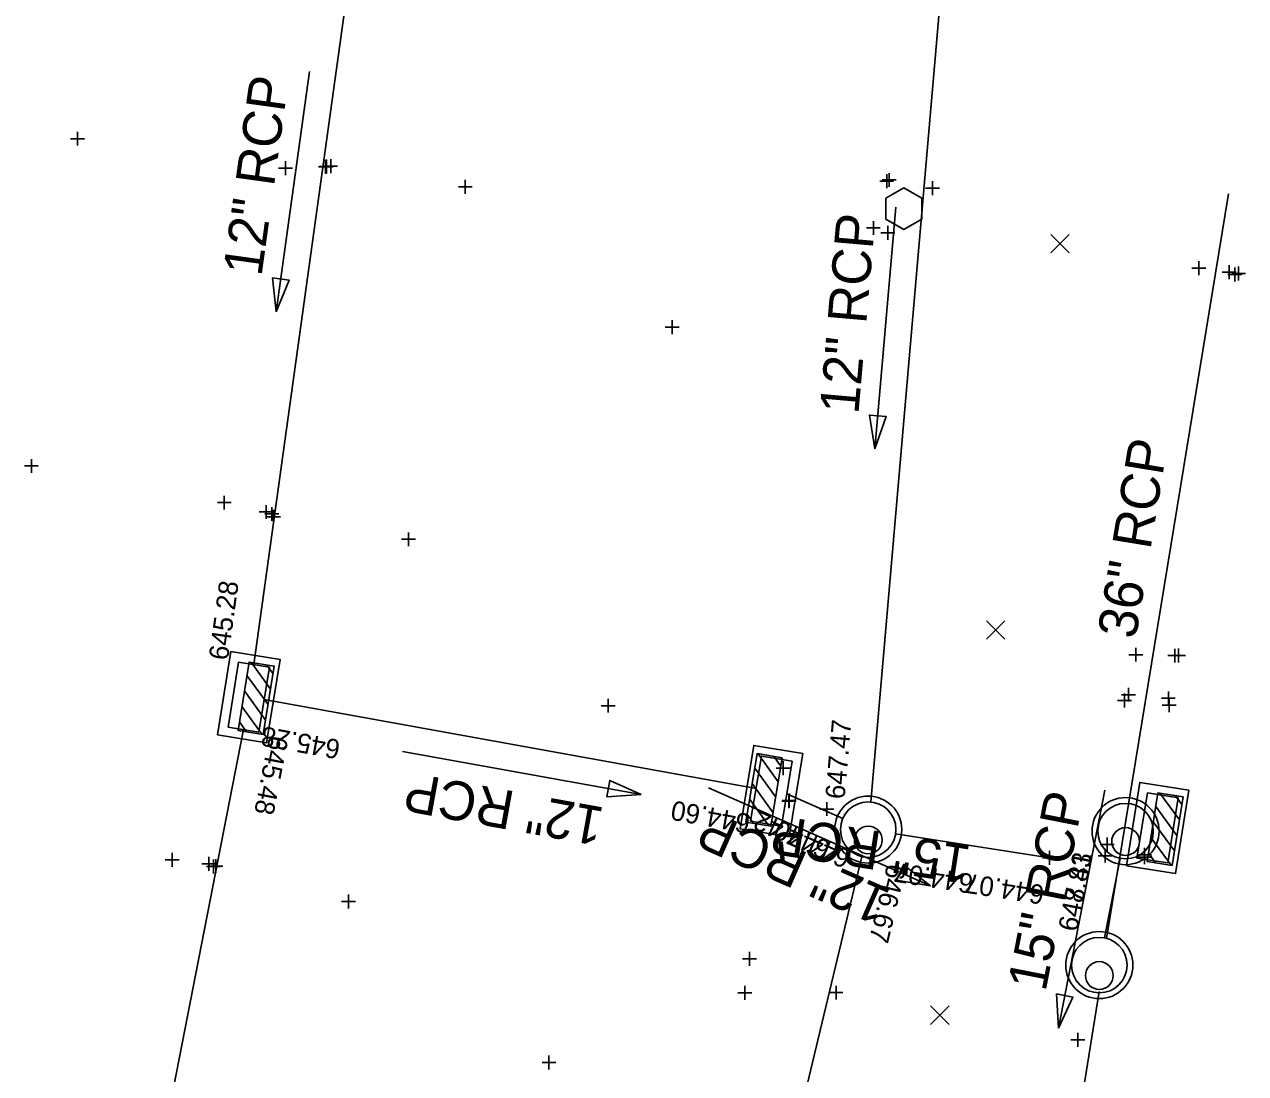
# Model space of a CAD drawing. Extents: x 2188719 to 2189819, y 654569 to 659504.
# Drawn here: x 2189545.4 to 2189633.4, y 656329.9 to 656405.5 of the extents above; entities that cross this region are included whole.
import ezdxf

# ---------------------------------------------------------------- set-up
doc = ezdxf.new("R2010")
doc.units = 0
for name, color, linetype in [('DR_X_Cells', 7, 'Continuous'), ('DR_X_Elev_Flow', 7, 'Continuous'), ('DR_X_Storm_Sewer', 7, 'Continuous'), ('DR_X_Text', 7, 'Continuous'), ('GK_Drainage_Nodes', 7, 'Continuous'), ('RD_X_Cells', 7, 'Continuous'), ('SC_Scratch1', 7, 'Continuous'), ('SV_X_Random_Point', 7, 'Continuous'), ('SV_X_Shot_Marker', 7, 'Continuous')]:
    doc.layers.add(name, color=color, linetype=linetype)

msp = doc.modelspace()

# ---------------------------------------------------------------- linework, layer by layer
at = {"layer": 'DR_X_Cells'}
for p, q in [((2189563.154, 656357.596), (2189561.755, 656359.529)), ((2189562.974, 656356.481), (2189561.456, 656358.578)), ((2189563.334, 656358.711), (2189562.874, 656359.348)), ((2189562.793, 656355.365), (2189561.275, 656357.463)), ((2189562.551, 656354.335), (2189561.095, 656356.348)), ((2189561.433, 656354.516), (2189560.914, 656355.232)), ((2189598.288, 656352.938), (2189599.736, 656350.92)), ((2189599.406, 656352.753), (2189599.921, 656352.035)), ((2189598.042, 656351.909), (2189599.551, 656349.805)), ((2189597.857, 656350.794), (2189599.366, 656348.691)), ((2189628.635, 656348.167), (2189627.233, 656350.098)), ((2189628.814, 656349.283), (2189628.352, 656349.919)), ((2189597.672, 656349.68), (2189599.063, 656347.741)), ((2189628.457, 656347.052), (2189626.935, 656349.147)), ((2189597.487, 656348.565), (2189597.945, 656347.927)), ((2189628.278, 656345.936), (2189626.757, 656348.031)), ((2189628.038, 656344.906), (2189626.578, 656346.915)), ((2189626.919, 656345.085), (2189626.4, 656345.8))]:
    msp.add_line(p, q, dxfattribs=at)
for points in [[(2189559.329, 656354.308), (2189560.301, 656360.313), (2189563.839, 656359.741), (2189562.867, 656353.735)], [(2189560.094, 656354.859), (2189560.853, 656359.548), (2189563.074, 656359.189), (2189562.315, 656354.5)], [(2189560.815, 656354.616), (2189561.613, 656359.552), (2189563.423, 656359.259), (2189562.624, 656354.323)], [(2189601.51, 656352.953), (2189600.515, 656346.951), (2189596.979, 656347.538), (2189597.974, 656353.539)], [(2189600.023, 656352.65), (2189599.205, 656347.718), (2189597.396, 656348.018), (2189598.215, 656352.95)], [(2189600.743, 656352.404), (2189599.965, 656347.718), (2189597.746, 656348.087), (2189598.523, 656352.772)], [(2189624.816, 656344.873), (2189625.777, 656350.879), (2189629.316, 656350.313), (2189628.355, 656344.306)], [(2189625.58, 656345.425), (2189626.331, 656350.116), (2189628.552, 656349.76), (2189627.802, 656345.07)], [(2189626.301, 656345.183), (2189627.091, 656350.121), (2189628.901, 656349.831), (2189628.111, 656344.894)]]:
    msp.add_lwpolyline(points, close=True, dxfattribs=at)
for centre, radius in [((2189606.217, 656347.475), 2.417), ((2189624.757, 656347.364), 2.417), ((2189606.217, 656347.475), 2), ((2189624.757, 656347.364), 2), ((2189606.217, 656346.725), 1), ((2189624.757, 656346.614), 1), ((2189622.866, 656337.708), 2.417), ((2189622.866, 656337.708), 2), ((2189622.866, 656336.958), 1)]:
    msp.add_circle(centre, radius, dxfattribs=at)
at = {"layer": 'DR_X_Elev_Flow'}
for p, q in [((2189618.782, 656345.442), (2189619.782, 656345.442)), ((2189619.282, 656345.942), (2189619.282, 656344.942)), ((2189619.282, 656345.442), (2189619.282, 656345.442)), ((2189603.396, 656335.723), (2189604.396, 656335.723)), ((2189603.896, 656336.223), (2189603.896, 656335.223)), ((2189603.896, 656335.723), (2189603.896, 656335.723))]:
    msp.add_line(p, q, dxfattribs=at)
at = {"layer": 'DR_X_Storm_Sewer'}
for p, q in [((2189571.657, 656429.364), (2189561.964, 656359.369)), ((2189612.494, 656419.834), (2189606.404, 656349.466)), ((2189623.386, 656339.617), (2189632.167, 656393.304)), ((2189562.695, 656356.844), (2189598.134, 656350.429)), ((2189547.183, 656282.894), (2189561.205, 656354.68)), ((2189600.354, 656350.061), (2189604.387, 656348.282)), ((2189608.193, 656347.168), (2189619.282, 656345.442)), ((2189589.745, 656278.758), (2189605.751, 656345.53)), ((2189624.373, 656345.401), (2189623.25, 656339.671)), ((2189622.866, 656335.815), (2189616.759, 656298.323))]:
    msp.add_line(p, q, dxfattribs=at)
at = {"layer": 'DR_X_Text'}
for p, q in [((2189565.963, 656402.099), (2189563.564, 656384.778)), ((2189608.207, 656392.329), (2189606.699, 656374.908)), ((2189572.654, 656353.111), (2189589.86, 656349.996)), ((2189594.702, 656350.478), (2189610.701, 656343.42)), ((2189623.274, 656350.328), (2189619.913, 656333.167))]:
    msp.add_line(p, q, dxfattribs=at)
for points in [[(2189563.564, 656384.778), (2189563.299, 656387.237), (2189564.488, 656387.073)], [(2189606.699, 656374.908), (2189606.308, 656377.351), (2189607.504, 656377.247)], [(2189589.86, 656349.996), (2189587.392, 656349.833), (2189587.605, 656351.014)], [(2189610.701, 656343.42), (2189608.263, 656343.84), (2189608.747, 656344.938)], [(2189619.913, 656333.167), (2189619.786, 656335.638), (2189620.963, 656335.407)]]:
    msp.add_lwpolyline(points, close=True, dxfattribs=at)
at = {"layer": 'GK_Drainage_Nodes'}
for p, q in [((2189561.964, 656359.369), (2189561.964, 656359.369)), ((2189559.816, 656357.31), (2189559.816, 656357.31)), ((2189560.474, 656357.204), (2189560.474, 656357.204)), ((2189561.214, 656357.084), (2189561.214, 656357.084)), ((2189561.214, 656357.084), (2189561.214, 656357.084)), ((2189561.584, 656357.024), (2189561.584, 656357.024)), ((2189562.695, 656356.844), (2189562.695, 656356.844)), ((2189563.353, 656356.738), (2189563.353, 656356.738)), ((2189561.205, 656354.68), (2189561.205, 656354.68)), ((2189599.633, 656352.588), (2189599.633, 656352.588)), ((2189597.477, 656350.539), (2189597.477, 656350.539)), ((2189598.134, 656350.429), (2189598.134, 656350.429)), ((2189599.244, 656350.245), (2189599.244, 656350.245)), ((2189599.614, 656350.184), (2189599.614, 656350.184)), ((2189599.614, 656350.184), (2189599.614, 656350.184)), ((2189600.354, 656350.061), (2189600.354, 656350.061)), ((2189601.012, 656349.952), (2189601.012, 656349.952)), ((2189627.442, 656349.938), (2189627.442, 656349.938)), ((2189606.217, 656349.475), (2189606.217, 656349.475)), ((2189624.757, 656349.364), (2189624.757, 656349.364)), ((2189598.855, 656347.902), (2189598.855, 656347.902)), ((2189606.217, 656347.475), (2189606.217, 656347.475)), ((2189606.217, 656347.475), (2189606.217, 656347.475)), ((2189624.757, 656347.364), (2189624.757, 656347.364)), ((2189624.757, 656347.364), (2189624.757, 656347.364)), ((2189625.297, 656347.876), (2189625.297, 656347.876)), ((2189625.955, 656347.771), (2189625.955, 656347.771)), ((2189626.696, 656347.652), (2189626.696, 656347.652)), ((2189626.696, 656347.652), (2189626.696, 656347.652)), ((2189627.066, 656347.593), (2189627.066, 656347.593)), ((2189628.177, 656347.415), (2189628.177, 656347.415)), ((2189628.835, 656347.31), (2189628.835, 656347.31)), ((2189606.217, 656346.725), (2189606.217, 656346.725)), ((2189624.757, 656346.614), (2189624.757, 656346.614)), ((2189606.217, 656345.475), (2189606.217, 656345.475)), ((2189624.757, 656345.364), (2189624.757, 656345.364)), ((2189626.691, 656345.248), (2189626.691, 656345.248)), ((2189622.866, 656339.708), (2189622.866, 656339.708)), ((2189622.866, 656337.708), (2189622.866, 656337.708)), ((2189622.866, 656337.708), (2189622.866, 656337.708)), ((2189622.866, 656336.958), (2189622.866, 656336.958)), ((2189622.866, 656335.708), (2189622.866, 656335.708))]:
    msp.add_line(p, q, dxfattribs=at)
for centre in [(2189606.217, 656347.475), (2189624.757, 656347.364), (2189622.866, 656337.708)]:
    msp.add_circle(centre, 2, dxfattribs=at)
at = {"layer": 'RD_X_Cells'}
msp.add_lwpolyline([(2189607.49, 656391.47), (2189608.788, 656390.72), (2189610.086, 656391.47), (2189610.086, 656392.97), (2189608.788, 656393.72), (2189607.49, 656392.97), (2189607.49, 656391.47)], dxfattribs=at)
at = {"layer": 'SV_X_Random_Point'}
for p, q in [((2189619.361, 656389.034), (2189620.695, 656390.368)), ((2189619.361, 656390.368), (2189620.695, 656389.034)), ((2189614.728, 656361.194), (2189616.062, 656362.529)), ((2189614.728, 656362.529), (2189616.062, 656361.194)), ((2189610.711, 656333.438), (2189612.045, 656334.772)), ((2189610.711, 656334.772), (2189612.045, 656333.438))]:
    msp.add_line(p, q, dxfattribs=at)
at = {"layer": 'SV_X_Shot_Marker'}
for p, q in [((2189548.743, 656397.266), (2189549.743, 656397.266)), ((2189549.243, 656397.766), (2189549.243, 656396.766)), ((2189549.243, 656397.266), (2189549.243, 656397.266)), ((2189564.23, 656395.64), (2189564.23, 656394.64)), ((2189567.117, 656395.739), (2189567.117, 656394.739)), ((2189567.18, 656395.761), (2189567.18, 656394.761)), ((2189567.488, 656395.781), (2189567.488, 656394.781)), ((2189563.73, 656395.14), (2189564.73, 656395.14)), ((2189564.23, 656395.14), (2189564.23, 656395.14)), ((2189566.617, 656395.239), (2189567.617, 656395.239)), ((2189566.68, 656395.261), (2189567.68, 656395.261)), ((2189566.988, 656395.281), (2189567.988, 656395.281)), ((2189567.117, 656395.239), (2189567.117, 656395.239)), ((2189567.18, 656395.261), (2189567.18, 656395.261)), ((2189567.488, 656395.281), (2189567.488, 656395.281)), ((2189607.548, 656394.709), (2189607.548, 656393.709)), ((2189607.721, 656394.79), (2189607.721, 656393.79)), ((2189576.687, 656393.8), (2189577.687, 656393.8)), ((2189577.187, 656394.3), (2189577.187, 656393.3)), ((2189577.187, 656393.8), (2189577.187, 656393.8)), ((2189607.048, 656394.209), (2189608.048, 656394.209)), ((2189607.221, 656394.29), (2189608.221, 656394.29)), ((2189607.548, 656394.209), (2189607.548, 656394.209)), ((2189607.721, 656394.29), (2189607.721, 656394.29)), ((2189610.849, 656394.198), (2189610.849, 656393.198)), ((2189610.349, 656393.698), (2189611.349, 656393.698)), ((2189610.849, 656393.698), (2189610.849, 656393.698)), ((2189606.585, 656391.334), (2189606.585, 656390.334)), ((2189606.085, 656390.834), (2189607.085, 656390.834)), ((2189606.585, 656390.834), (2189606.585, 656390.834)), ((2189607.127, 656390.474), (2189608.127, 656390.474)), ((2189607.627, 656390.974), (2189607.627, 656389.974)), ((2189607.627, 656390.474), (2189607.627, 656390.474)), ((2189629.54, 656387.942), (2189630.54, 656387.942)), ((2189630.04, 656388.442), (2189630.04, 656387.442)), ((2189630.04, 656387.942), (2189630.04, 656387.942)), ((2189631.714, 656387.649), (2189632.714, 656387.649)), ((2189632.214, 656388.149), (2189632.214, 656387.149)), ((2189632.214, 656387.649), (2189632.214, 656387.649)), ((2189632.636, 656387.983), (2189632.636, 656386.983)), ((2189632.903, 656388.045), (2189632.903, 656387.045)), ((2189632.136, 656387.483), (2189633.136, 656387.483)), ((2189632.403, 656387.545), (2189633.403, 656387.545)), ((2189632.636, 656387.483), (2189632.636, 656387.483)), ((2189632.903, 656387.545), (2189632.903, 656387.545)), ((2189592.086, 656384.182), (2189592.086, 656383.182)), ((2189591.586, 656383.682), (2189592.586, 656383.682)), ((2189592.086, 656383.682), (2189592.086, 656383.682)), ((2189545.424, 656373.679), (2189546.424, 656373.679)), ((2189545.924, 656374.179), (2189545.924, 656373.179)), ((2189545.924, 656373.679), (2189545.924, 656373.679)), ((2189559.325, 656371.037), (2189560.325, 656371.037)), ((2189559.825, 656371.537), (2189559.825, 656370.537)), ((2189559.825, 656371.037), (2189559.825, 656371.037)), ((2189562.84, 656370.864), (2189562.84, 656369.864)), ((2189562.34, 656370.364), (2189563.34, 656370.364)), ((2189562.743, 656370.223), (2189563.743, 656370.223)), ((2189562.84, 656370.364), (2189562.84, 656370.364)), ((2189562.872, 656370.011), (2189563.872, 656370.011)), ((2189563.243, 656370.723), (2189563.243, 656369.723)), ((2189563.243, 656370.223), (2189563.243, 656370.223)), ((2189563.372, 656370.511), (2189563.372, 656369.511)), ((2189563.372, 656370.011), (2189563.372, 656370.011)), ((2189572.588, 656368.394), (2189573.588, 656368.394)), ((2189573.088, 656368.894), (2189573.088, 656367.894)), ((2189573.088, 656368.394), (2189573.088, 656368.394)), ((2189625.504, 656360.577), (2189625.504, 656359.577)), ((2189628.307, 656360.511), (2189628.307, 656359.511)), ((2189628.565, 656360.519), (2189628.565, 656359.519)), ((2189625.004, 656360.077), (2189626.004, 656360.077)), ((2189625.504, 656360.077), (2189625.504, 656360.077)), ((2189627.807, 656360.011), (2189628.807, 656360.011)), ((2189628.065, 656360.019), (2189629.065, 656360.019)), ((2189628.307, 656360.011), (2189628.307, 656360.011)), ((2189628.565, 656360.019), (2189628.565, 656360.019)), ((2189624.962, 656357.694), (2189624.962, 656356.694)), ((2189587.481, 656356.903), (2189587.481, 656355.903)), ((2189624.176, 656356.773), (2189625.176, 656356.773)), ((2189624.462, 656357.194), (2189625.462, 656357.194)), ((2189624.676, 656357.273), (2189624.676, 656356.273)), ((2189624.676, 656356.773), (2189624.676, 656356.773)), ((2189624.962, 656357.194), (2189624.962, 656357.194)), ((2189627.339, 656356.936), (2189628.339, 656356.936)), ((2189627.839, 656357.436), (2189627.839, 656356.436)), ((2189627.839, 656356.936), (2189627.839, 656356.936)), ((2189627.895, 656356.93), (2189627.895, 656355.93)), ((2189586.981, 656356.403), (2189587.981, 656356.403)), ((2189587.481, 656356.403), (2189587.481, 656356.403)), ((2189627.395, 656356.43), (2189628.395, 656356.43)), ((2189627.895, 656356.43), (2189627.895, 656356.43)), ((2189600.089, 656352.407), (2189600.089, 656351.407)), ((2189599.589, 656351.907), (2189600.589, 656351.907)), ((2189600.089, 656351.907), (2189600.089, 656351.907)), ((2189600.503, 656350.014), (2189600.503, 656349.014)), ((2189600.517, 656350.077), (2189600.517, 656349.077)), ((2189600.003, 656349.514), (2189601.003, 656349.514)), ((2189600.017, 656349.577), (2189601.017, 656349.577)), ((2189600.503, 656349.514), (2189600.503, 656349.514)), ((2189600.517, 656349.577), (2189600.517, 656349.577)), ((2189602.738, 656348.955), (2189603.738, 656348.955)), ((2189603.238, 656349.455), (2189603.238, 656348.455)), ((2189603.238, 656348.955), (2189603.238, 656348.955)), ((2189622.932, 656346.4), (2189623.932, 656346.4)), ((2189623.432, 656346.9), (2189623.432, 656345.9)), ((2189623.432, 656346.4), (2189623.432, 656346.4)), ((2189556.075, 656345.802), (2189556.075, 656344.802)), ((2189558.716, 656345.504), (2189558.716, 656344.504)), ((2189559.212, 656345.35), (2189559.212, 656344.35)), ((2189622.781, 656345.595), (2189623.781, 656345.595)), ((2189623.281, 656346.095), (2189623.281, 656345.095)), ((2189623.281, 656345.595), (2189623.281, 656345.595)), ((2189625.619, 656345.484), (2189626.619, 656345.484)), ((2189625.631, 656345.66), (2189626.631, 656345.66)), ((2189626.119, 656345.984), (2189626.119, 656344.984)), ((2189626.119, 656345.484), (2189626.119, 656345.484)), ((2189626.131, 656346.16), (2189626.131, 656345.16)), ((2189626.131, 656345.66), (2189626.131, 656345.66)), ((2189555.575, 656345.302), (2189556.575, 656345.302)), ((2189556.075, 656345.302), (2189556.075, 656345.302)), ((2189558.216, 656345.004), (2189559.216, 656345.004)), ((2189558.541, 656344.818), (2189559.541, 656344.818)), ((2189558.712, 656344.85), (2189559.712, 656344.85)), ((2189558.716, 656345.004), (2189558.716, 656345.004)), ((2189559.041, 656345.318), (2189559.041, 656344.318)), ((2189559.041, 656344.818), (2189559.041, 656344.818)), ((2189559.212, 656344.85), (2189559.212, 656344.85)), ((2189568.767, 656342.787), (2189568.767, 656341.787)), ((2189568.267, 656342.287), (2189569.267, 656342.287)), ((2189568.767, 656342.287), (2189568.767, 656342.287)), ((2189597.667, 656338.668), (2189597.667, 656337.668)), ((2189597.167, 656338.168), (2189598.167, 656338.168)), ((2189597.667, 656338.168), (2189597.667, 656338.168)), ((2189596.824, 656335.715), (2189597.824, 656335.715)), ((2189597.324, 656336.215), (2189597.324, 656335.215)), ((2189597.324, 656335.715), (2189597.324, 656335.715)), ((2189620.816, 656332.328), (2189621.816, 656332.328)), ((2189621.316, 656332.828), (2189621.316, 656331.828)), ((2189621.316, 656332.328), (2189621.316, 656332.328)), ((2189582.717, 656330.694), (2189583.717, 656330.694)), ((2189583.217, 656331.194), (2189583.217, 656330.194)), ((2189583.217, 656330.694), (2189583.217, 656330.694))]:
    msp.add_line(p, q, dxfattribs=at)

# ---------------------------------------------------------------- texts
at = {"layer": 'DR_X_Text'}
for s, rotation, p in [('12" RCP', 82.1157, (2189562.498, 656387.288)), ('12" RCP', 85.05382, (2189605.506, 656377.36)), ('36" RCP', 80.71157, (2189625.488, 656361.14)), ('12" RCP', 169.73998, (2189587.308, 656349.036)), ('15" RCP', 78.91961, (2189618.989, 656335.733)), ('12" RCP', 156.19745, (2189607.995, 656343.084)), ('15" RCP', 171.15576, (2189613.738, 656346.305))]:
    msp.add_text(s, height=2.8, rotation=rotation, dxfattribs=at).set_placement(p)
at = {"layer": 'SC_Scratch1'}
for s, rotation, p in [('645.28', 82.1157, (2189560.082, 656359.629)), ('647.47', 85.05382, (2189604.511, 656349.63)), ('645.48', 258.94735, (2189563.07, 656354.315)), ('645.28', 169.73998, (2189568.256, 656353.907)), ('644.60', 169.73998, (2189597.796, 656348.56)), ('644.42', 156.19745, (2189603.62, 656346.544)), ('644.70', 156.19745, (2189605.075, 656345.902)), ('647.83', 78.91961, (2189621.263, 656340.06)), ('648.41', 78.91961, (2189621.265, 656340.07)), ('646.67', 256.52028, (2189607.598, 656345.087)), ('644.07', 171.15576, (2189613.867, 656344.235)), ('644.07', 171.15576, (2189618.971, 656343.441))]:
    msp.add_text(s, height=1.4, rotation=rotation, dxfattribs=at).set_placement(p)

doc.saveas('drawing.dxf')
